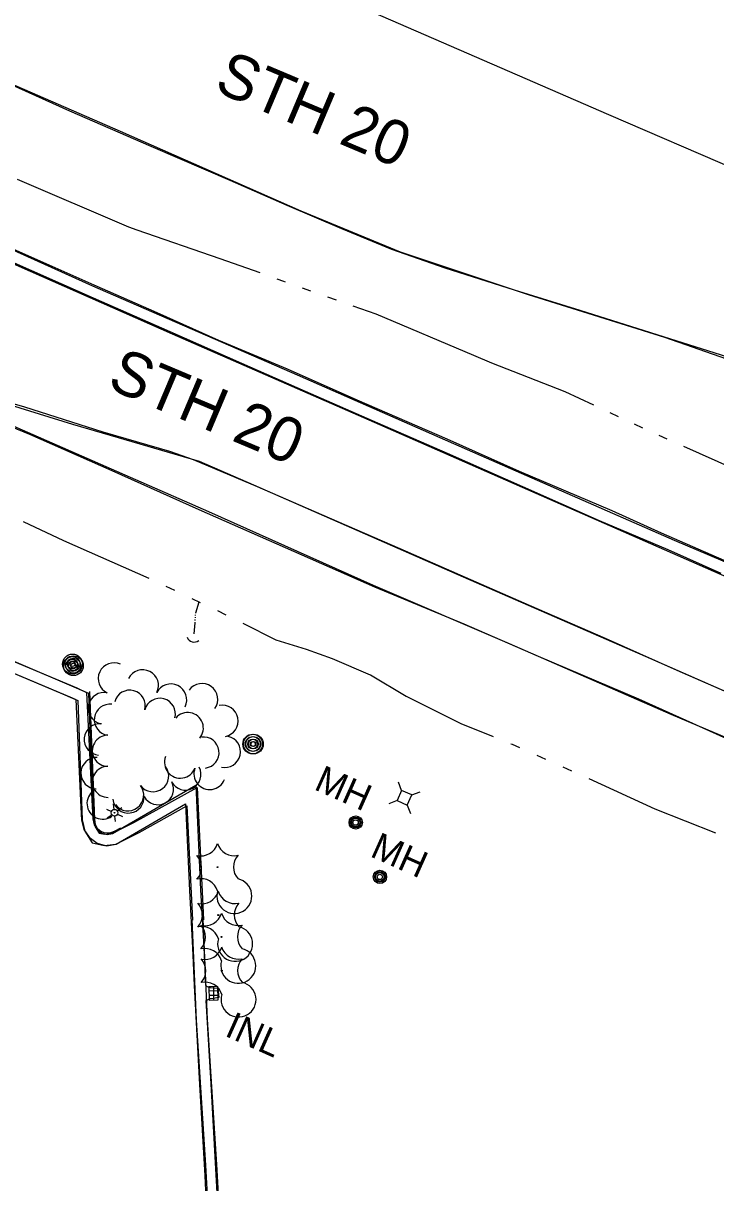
# Model space of a CAD drawing. Extents: x 588843 to 2552415, y 180129 to 269402.
# Drawn here: x 594936.7 to 595092.6, y 184873.1 to 185134.3 of the extents above; entities that cross this region are included whole.
import ezdxf

# ---------------------------------------------------------------- set-up
doc = ezdxf.new("R2010")
doc.units = 0
for name, color, linetype in [('Default', 7, 'Continuous'), ('E_DRN', 7, 'Continuous'), ('E_DRN_Text', 7, 'Continuous'), ('E_DWY', 7, 'Continuous'), ('E_LAND_TreeLine_P', 7, 'Continuous'), ('E_LAND_Vegetation', 7, 'Continuous'), ('E_LTG', 7, 'Continuous'), ('E_MISCPROP', 7, 'Continuous'), ('E_RDWY', 7, 'Continuous'), ('E_RDWY_C_and_G', 7, 'Continuous'), ('E_RDWY_Gravel', 7, 'Continuous'), ('E_RDWY_Text', 7, 'Continuous'), ('E_UTL_AG_Bold', 7, 'Continuous'), ('E_UTL_MH', 7, 'Continuous'), ('E_UTL_MH_Text', 7, 'Continuous'), ('E_WTR_P', 7, 'Continuous')]:
    doc.layers.add(name, color=color, linetype=linetype)

# ---------------------------------------------------------------- blocks, each defined once
blk = doc.blocks.new('POLE')
at = {"layer": 'Default'}
for radius in [4.46, 3.35, 2.23, 1.12]:
    blk.add_circle((0, 0), radius, dxfattribs=at)
blk = doc.blocks.new('PED')
at = {"layer": 'Default'}
for p, q in [((-2.5, 2.5), (-5.33, 5.33)), ((2.5, 2.5), (5.33, 5.33)), ((-2.5, -2.5), (-5.33, -5.33)), ((2.5, -2.5), (5.33, -5.33))]:
    blk.add_line(p, q, dxfattribs=at)
blk.add_lwpolyline([(-2.5, -2.5), (2.5, -2.5), (2.5, 2.5), (-2.5, 2.5)], close=True, dxfattribs=at)
blk = doc.blocks.new('MHO')
at = {"layer": 'Default'}
for centre, radius in [((0.08, -0.12), 3), ((0.08, -0.12), 2.43), ((0.07, -0.15), 1.94), ((0.02, -0.16), 1.21)]:
    blk.add_circle(centre, radius, dxfattribs=at)
blk = doc.blocks.new('MHT')
at = {"layer": 'E_UTL_MH_Text'}
blk.add_text('MH', height=12, dxfattribs=at).set_placement((-9.81, -6))
blk = doc.blocks.new('INLO')
at = {"layer": 'E_DRN'}
for p, q in [((2, -4), (2, 0)), ((4, -4), (4, 0)), ((6, -2), (0, -2))]:
    blk.add_line(p, q, dxfattribs=at)
blk.add_lwpolyline([(0, -4), (6, -4), (6, 0), (0, 0), (0, -4)], close=True, dxfattribs=at)
blk = doc.blocks.new('INLT_22')
at = {"layer": 'E_DRN_Text'}
blk.add_text('INL', height=12, dxfattribs=at).set_placement((-11.03, -6))
blk = doc.blocks.new('LPOL')
at = {"layer": 'Default'}
for p, q in [((-4, 0), (-1.5, 0)), ((-0.75, 1.3), (-2, 3.46)), ((0.75, 1.3), (2, 3.46)), ((1.5, 0), (4, 0)), ((-2, -3.46), (-0.75, -1.3)), ((2, -3.46), (0.75, -1.3))]:
    blk.add_line(p, q, dxfattribs=at)
for radius in [1.5, 1.5, 1.5, 0.125]:
    blk.add_circle((0, 0), radius, dxfattribs=at)
blk = doc.blocks.new('CTRE')
at = {"layer": 'Default'}
blk.add_circle((0, 0), 0.223, dxfattribs=at)
for centre, start, end in [((-11.97, 8.96), 280.2067, 5.9716), ((1.81, 14.92), 220.2113, 305.9762), ((13.83, 5.89), 160.2113, 245.9762), ((-13.83, -5.9), 340.2113, 65.9762), ((12.03, -9.04), 185.9272, 100.2511), ((-1.81, -14.93), 40.2113, 125.9762)]:
    blk.add_arc(centre, 7.87, start, end, dxfattribs=at)
blk = doc.blocks.new('POLE_3')
at = {"layer": 'E_MISCPROP'}
for radius in [14.6, 11, 7.32, 3.66]:
    blk.add_circle((0, 0), radius, dxfattribs=at)
blk = doc.blocks.new('CULV2_4')
at = {"layer": 'E_DRN'}
blk.add_arc((65, 48), 80.7, 216.8699, 323.1301, dxfattribs=at)

msp = doc.modelspace()

# ---------------------------------------------------------------- linework, layer by layer
at = {"layer": 'E_DWY'}
for points in [[(594875.58, 185012.63), (594890, 185006.61), (594906.61, 184999.61), (594919.3, 184994.16), (594934.73, 184987.79), (594947.71, 184982.35), (594948.54, 184981.95), (594949.63, 184959.24), (594949.85, 184954.76), (594950.38, 184952.7), (594951.56, 184950.95), (594953.31, 184949.6), (594955.43, 184949.05), (594957.6, 184949.36), (594973.26, 184958.44), (594974.11, 184938.99), (594974.84, 184926.05), (594975.21, 184917.53)], [(594880.13, 185013.4), (594890.96, 185008.92), (594907.59, 185001.91), (594920.27, 184996.47), (594935.69, 184990.1), (594948.74, 184984.63), (594950.96, 184983.54), (594952.13, 184959.36), (594952.34, 184955.13), (594952.69, 184953.74), (594953.41, 184952.68), (594954.43, 184951.89), (594955.58, 184951.59), (594956.77, 184951.76), (594975.58, 184962.67), (594976.6, 184939.12), (594977.34, 184926.17), (594977.71, 184917.64)], [(594902.2, 185004.23), (594928.88, 184993.01), (594946.5, 184985.51), (594951.42, 184983.39), (594952.48, 184955.24), (594952.93, 184953.26), (594953.77, 184951.9), (594955.03, 184951.64), (594956.83, 184951.84), (594961.62, 184954.26), (594975.86, 184962.16), (594977.26, 184932.37)], [(594901.23, 185001.93), (594927.91, 184990.71), (594945.51, 184983.22), (594948.98, 184981.72), (594949.99, 184954.9), (594950.59, 184952.3), (594952.21, 184949.66), (594954.92, 184949.11), (594957.55, 184949.41), (594962.79, 184952.05), (594973.55, 184958.02), (594974.77, 184932.26)], [(594974.66, 184932.39), (594975.61, 184909.78), (594977.73, 184877.11), (594978.24, 184867.66), (594964.37, 184859.04), (594962.71, 184857.32), (594961.61, 184855), (594961.12, 184851.95), (594961.17, 184850.76)], [(594977.16, 184932.49), (594978.11, 184909.91), (594980.23, 184877.26), (594980.87, 184865.2), (594979.03, 184865.21), (594965.96, 184857.08), (594964.79, 184855.87), (594964.02, 184854.25), (594963.63, 184851.8), (594963.67, 184850.87)], [(594977.71, 184917.64), (594977.91, 184917.44), (594978.8, 184917.08), (594980.5, 184916.93), (594980.7, 184914.89), (594979.45, 184914.65), (594978.74, 184914.53), (594977.83, 184914.14)], [(594975.21, 184917.53), (594976.41, 184895.24), (594977.55, 184874.8), (594977.92, 184867.99), (594968.68, 184862.39), (594963.39, 184858.96), (594961.56, 184856.18), (594961, 184854.17), (594960.76, 184851.77), (594960.87, 184847.27), (594961.51, 184844.88), (594963.12, 184842.74), (594965.77, 184842.06), (594967.7, 184842.28), (594978.98, 184848.12), (594979.73, 184831.96), (594980.92, 184811.23)], [(594977.83, 184914.19), (594978.9, 184895.38), (594980.04, 184874.94), (594980.55, 184865.6), (594978.81, 184865.61), (594970, 184860.28), (594965.19, 184857.15), (594963.87, 184855.14), (594963.47, 184853.7), (594963.26, 184851.68), (594963.36, 184847.63), (594963.8, 184846), (594964.59, 184844.94), (594965.95, 184844.6), (594966.96, 184844.71), (594980.19, 184851.55), (594981.33, 184851.57), (594982.23, 184832.09), (594983.34, 184812.67)]]:
    msp.add_lwpolyline(points, dxfattribs=at)
at = {"layer": 'E_LAND_TreeLine_P'}
for centre, radius, start, end in [((594957.13, 184986.68), 3.55, 65.0576, 245.0576), ((594963.6, 184985.1), 3.55, 333.491, 153.491), ((594976.94, 184982.03), 3.55, 324.2313, 144.2313), ((594954.89, 184980), 3.55, 77.9754, 257.9754), ((594960.68, 184980.56), 3.51, 344.8889, 164.8889), ((594969.95, 184981.93), 3.55, 333.491, 153.491), ((594956.19, 184977.41), 3.51, 82.1144, 262.1144), ((594967.45, 184978.73), 3.51, 344.8889, 164.8889), ((594981.54, 184977.14), 3.55, 281.3298, 101.3298), ((594973.74, 184975.53), 3.51, 319.7836, 139.7836), ((594953.98, 184972.98), 3.55, 84.8145, 264.8145), ((594955.76, 184970.43), 3.51, 90.2162, 270.2162), ((594977.28, 184970.02), 3.51, 277.3753, 97.3753), ((594982.07, 184970.19), 3.55, 257.6066, 77.6066), ((594953.23, 184965.39), 3.55, 88.6511, 268.6511), ((594972.06, 184967.81), 3.55, 158.7157, 338.7157), ((594955.79, 184963.42), 3.51, 90.2162, 270.2162), ((594965.91, 184964.74), 3.55, 217.3559, 37.3559), ((594973.21, 184965.08), 3.51, 208.0364, 28.0364), ((594978.67, 184965.23), 3.55, 158.7157, 338.7157), ((594960.27, 184960.44), 3.55, 217.3559, 37.3559), ((594967.02, 184961.78), 3.51, 208.0364, 28.0364), ((594954.6, 184958.57), 3.55, 125.3704, 305.3704), ((594960.39, 184959.9), 3.51, 186.6125, 6.6125)]:
    msp.add_arc(centre, radius, start, end, dxfattribs=at)
at = {"layer": 'E_RDWY'}
for points in [[(594953.31, 185166.36), (594958.15, 185162.28), (594975.56, 185154.43), (594999.99, 185143.55), (595034.76, 185128.38), (595068.45, 185113.72), (595097.34, 185101.25), (595121.56, 185090.33), (595130.22, 185086.62), (595134.71, 185084.42)], [(594925.9, 185124.17), (594958.5, 185109.94), (594999.16, 185092.06), (595021.58, 185082.77), (595050.38, 185073.2), (595081.02, 185063.61), (595102.72, 185056.02)], [(594926.41, 185123.84), (594947.09, 185114.58), (594965.39, 185106.61), (594983.19, 185098.92), (594996.06, 185093.29), (595008.35, 185088.08), (595019.6, 185083.37), (595031.64, 185079.16), (595047.2, 185074.24), (595062, 185069.68), (595095.23, 185059.13)], [(594897.33, 185099.5), (594896.3, 185097.34), (594929.83, 185082.12), (594970.2, 185064.32), (595016.88, 185043.89), (595058.26, 185025.7), (595093.29, 185010.35), (595106.31, 185004.68)], [(595093.78, 185010.36), (595081.85, 185015.66), (595066.4, 185022.21), (595049.2, 185029.86), (595032.18, 185037.35), (595016.49, 185044.18), (595000.22, 185051.32), (594985.89, 185057.65), (594969.81, 185064.77), (594952.53, 185072.36), (594931.31, 185081.72)], [(595098.71, 184982.04), (595083.93, 184988.5), (595067.8, 184995.72), (595050.7, 185003.11), (595036.24, 185009.41), (595021.57, 185015.87), (595005.62, 185022.78), (594989.44, 185029.87), (594975.03, 185035.94), (594969.71, 185037.84), (594954.73, 185042.17), (594937.03, 185047.81), (594919.92, 185052.73), (594908.19, 185056.29), (594894.77, 185060.43), (594883.38, 185063.87), (594878.29, 185065.81)], [(594878.43, 185065.29), (594911.2, 185055.3), (594947.8, 185044), (594976.33, 185035.64), (594988.52, 185030.3), (595035.74, 185009.62), (595076.71, 184991.76), (595101.16, 184980.97)]]:
    msp.add_lwpolyline(points, dxfattribs=at)
at = {"layer": 'E_RDWY_C_and_G'}
msp.add_lwpolyline([(594951.61, 184983.74), (594952.76, 184954.95), (594952.9, 184953.81), (594952.9, 184953.81), (594953.36, 184953.02), (594953.36, 184953.02), (594953.97, 184952.46), (594953.97, 184952.46), (594954.34, 184952.22), (594954.34, 184952.22), (594954.87, 184952.04), (594954.87, 184952.04), (594955.76, 184951.92), (594955.76, 184951.92), (594956.42, 184951.99), (594956.42, 184951.99), (594957.25, 184952.35), (594957.25, 184952.35), (594958.69, 184953.06)], dxfattribs=at)
at = {"layer": 'E_RDWY_Gravel'}
for points in [[(595098.65, 185011.51), (595080.37, 185019.45), (595069.25, 185024.45), (595048.4, 185033.3), (595032.11, 185040.59), (595011.9, 185049.39), (594996.16, 185056.38), (594980.77, 185062.83), (594966.82, 185069.09), (594952.68, 185075.32), (594935.11, 185083.12), (594920.43, 185089.79), (594903.67, 185097.13), (594892.65, 185102.39)], [(594897.33, 185099.5), (594919.84, 185089.79), (594952.31, 185075.17), (594998.39, 185055.12), (595039.68, 185036.96), (595083.25, 185017.84), (595107.08, 185007.74)], [(595125.52, 184959.34), (595075.29, 184982.01), (595052.68, 184991.66), (595035.98, 184998.92), (595015.83, 185007.26), (594997.64, 185015.28), (594976.31, 185024.69), (594956.73, 185033.45), (594938.19, 185041.65), (594920.92, 185048.72), (594907.85, 185054.11), (594895.48, 185058.78), (594877.44, 185063.46)], [(594877.78, 185063.02), (594898.63, 185057.15), (594912.24, 185052.85), (594926.64, 185046.99), (594949.85, 185036.86), (594978.4, 185024.29), (595015.45, 185007.75), (595046.08, 184994.58), (595082.47, 184978.64), (595101.48, 184970.64)]]:
    msp.add_lwpolyline(points, dxfattribs=at)
at = {"layer": 'E_WTR_P'}
for points in [[(594935.32, 185099.19), (594960.38, 185088.44), (594962.31, 185087.77)], [(594962.31, 185087.77), (594980.97, 185081.32), (594989.98, 185078.1)], [(594993.78, 185076.74), (594995.28, 185076.2), (594995.69, 185076.06)], [(594999.5, 185074.7), (595001.4, 185074.03)], [(595005.21, 185072.67), (595007.12, 185072)], [(595010.93, 185070.65), (595016.1, 185068.81), (595038.03, 185059.51)], [(595038.03, 185059.51), (595042.12, 185057.78), (595058.6, 185051.32), (595065.1, 185048.3)], [(595068.76, 185046.59), (595070.6, 185045.74)], [(595074.26, 185044.03), (595076.1, 185043.18)], [(595079.76, 185041.48), (595081.61, 185040.66)], [(595085.3, 185039.01), (595112.08, 185027.11)], [(594936.7, 185022.03), (594945.76, 185017.75), (594964.96, 185009.32)], [(594968.84, 185007.51), (594970.76, 185006.59)], [(594974.62, 185004.75), (594976.55, 185003.82)], [(594975.53, 185001.42), (594975.53, 185001.5), (594976.32, 185003.93)], [(594980.41, 185001.98), (594982.33, 185001.06), (594982.34, 185001.06)], [(594975.19, 184996.79), (594975.39, 184999.24), (594975.4, 184999.42)], [(594975.42, 184999.79), (594975.43, 184999.97)], [(594975.46, 185000.33), (594975.47, 185000.51)], [(594975.49, 185000.88), (594975.5, 185001.06)], [(594986.16, 184999.15), (594993.57, 184995.44), (595000.38, 184993.29), (595006.21, 184991.22), (595014.79, 184987.56), (595014.84, 184987.53)], [(595014.84, 184987.53), (595022.94, 184982.72), (595035.23, 184976.59), (595042.49, 184973.63)], [(595046.45, 184972.01), (595046.73, 184971.9), (595048.41, 184971.15)], [(595052.31, 184969.41), (595054.26, 184968.54)], [(595058.17, 184966.79), (595060.12, 184965.92)], [(595064.02, 184964.16), (595078.9, 184957.37), (595092.51, 184951.97)]]:
    msp.add_lwpolyline(points, dxfattribs=at)

# ---------------------------------------------------------------- block references
at = {"layer": 'E_DRN'}
for name, p, xscale, yscale, rotation in [('CULV2_4', (594973.57, 184996.02), 0.021343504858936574, 0.02134350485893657, -15.969778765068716), ('INLO', (594978.57, 184914.29), 0.5, 0.5, 91.33954420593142)]:
    msp.add_blockref(name, p, dxfattribs=dict(at, xscale=xscale, yscale=yscale, rotation=rotation))
at = {"layer": 'E_DRN_Text', "xscale": 0.49999999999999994, "yscale": 0.49999999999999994, "rotation": -24.085783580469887}
msp.add_blockref('INLT_22', (594988.08, 184906.81), dxfattribs=at)
at = {"layer": 'E_LAND_Vegetation', "xscale": 0.4999999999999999, "yscale": 0.5, "rotation": -22.87015224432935}
for p in [(594980.44, 184944.21), (594980.62, 184933.43), (594981.33, 184928.49), (594981.39, 184920.9)]:
    msp.add_blockref('CTRE', p, dxfattribs=at)
at = {"layer": 'E_LTG', "xscale": 0.49999999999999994, "yscale": 0.49999999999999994, "rotation": -24.085783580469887}
msp.add_blockref('LPOL', (594957.25, 184956.47), dxfattribs=at)
at = {"layer": 'E_MISCPROP'}
for name, p, xscale, yscale, rotation in [('POLE', (594947.79, 184989.96), 0.49999999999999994, 0.49999999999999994, -24.085783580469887), ('POLE_3', (594948, 184989.58), 0.15240030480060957, 0.15240030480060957, 0.8014450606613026), ('POLE', (594988.37, 184971.94), 0.49999999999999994, 0.49999999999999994, -24.085783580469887), ('POLE_3', (594988.52, 184971.94), 0.15240030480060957, 0.15240030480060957, 0.8014450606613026)]:
    msp.add_blockref(name, p, dxfattribs=dict(at, xscale=xscale, yscale=yscale, rotation=rotation))
at = {"layer": 'E_UTL_AG_Bold', "xscale": 0.49999999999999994, "yscale": 0.49999999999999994, "rotation": -24.085783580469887}
msp.add_blockref('PED', (595022.51, 184959.85), dxfattribs=at)
at = {"layer": 'E_UTL_MH', "xscale": 0.49999999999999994, "yscale": 0.49999999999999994, "rotation": -24.085783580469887}
for p in [(595011.53, 184954.34), (595017, 184942.09)]:
    msp.add_blockref('MHO', p, dxfattribs=at)
at = {"layer": 'E_UTL_MH_Text', "xscale": 0.49999999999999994, "yscale": 0.49999999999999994, "rotation": -24.085783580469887}
for p in [(595007.62, 184962.56), (595020.25, 184947.47)]:
    msp.add_blockref('MHT', p, dxfattribs=at)

# ---------------------------------------------------------------- texts
at = {"layer": 'E_RDWY_Text'}
for p in [(594979.37, 185119.16), (594955.28, 185052.24)]:
    msp.add_text('STH 20', height=10, rotation=337.1357, dxfattribs=at).set_placement(p)

doc.saveas('drawing.dxf')
